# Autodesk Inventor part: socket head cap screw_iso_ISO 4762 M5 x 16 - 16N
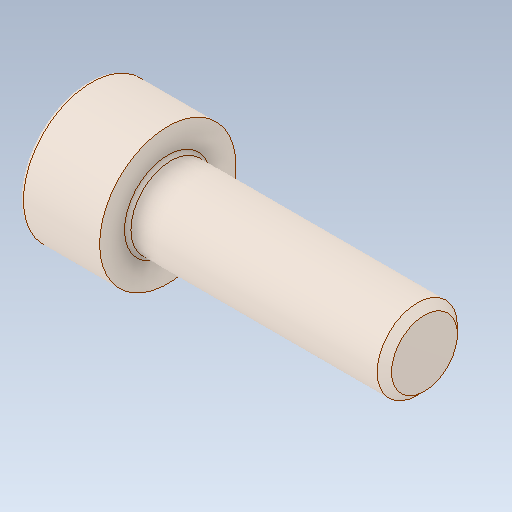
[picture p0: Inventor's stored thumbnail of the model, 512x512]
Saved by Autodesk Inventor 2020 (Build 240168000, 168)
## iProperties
Created: 1999-08
Part Number: socket head cap screw_iso_ISO 4762 M5 x 16 - 16N
Material: Ogólny
Document SubType Name: Modeling
Designer: Tomasz
Density: 1 g/cm^3
Appearance: Domyślna
Sending System: SolidWorks 2017
Last Author: Tomasz
Last Saved: 2017-11-19
Author: Tomasz
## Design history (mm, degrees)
feature "Hex"
node "Bryła1"
